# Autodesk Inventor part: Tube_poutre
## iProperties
Shininess: 64.0
Length Units: 11269
Angle Units: 11279
Time Units: 11290
Mass Units: 11283
Length Display Precision: 3
Angle Display Precision: 2
Compacted: True
Part Number: Tube_poutre
Document SubType Name: Modeling
Created: 2008-04
Material: Par défaut
Designer: Pascal
Density: 0.0
Volumn: 0.0
Area: 0.0
PropertySet Name: Model Information
Control State: 0
Master: False
Checked Out: False
DESIGNATION: pièce
Author: Pascal
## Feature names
1. Extrusion1
